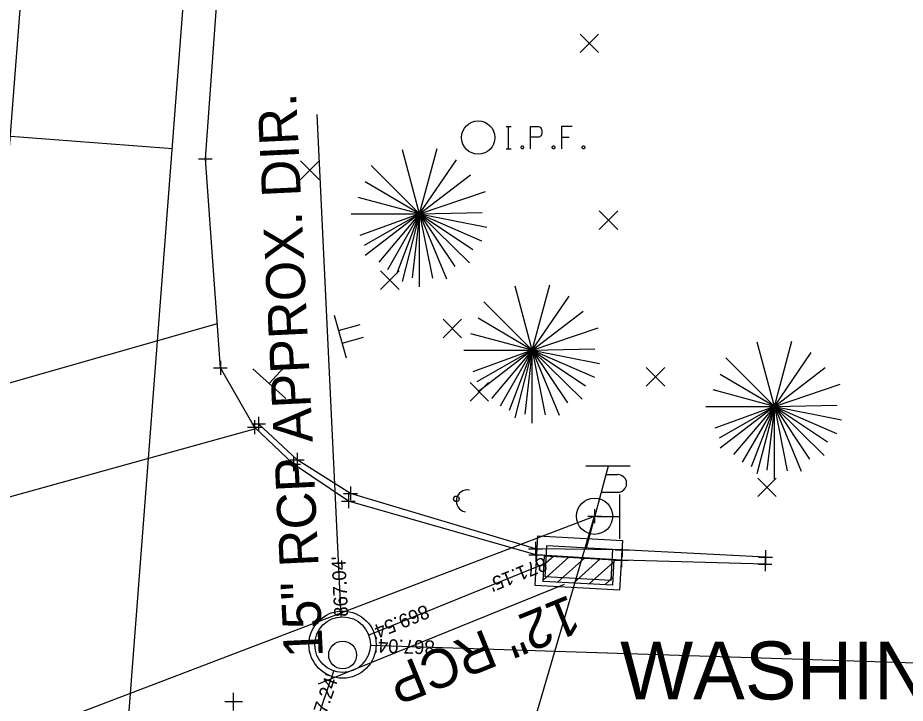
# Model space of a CAD drawing. Extents: x 1380440 to 1381945, y 468756 to 470369.
# Drawn here: x 1381624.1 to 1381687.9, y 470234 to 470283.3 of the extents above; entities that cross this region are included whole.
import ezdxf

# ---------------------------------------------------------------- set-up
doc = ezdxf.new("R2010")
doc.units = 0
for name, color, linetype in [('Animation Elements', 7, 'Continuous'), ('DR_X_Cells', 7, 'Continuous'), ('DV_X_Text', 7, 'Continuous'), ('GE_P_Driveway_CL', 7, 'Continuous'), ('PM_X_Crosswalk', 7, 'Continuous'), ('PV_P_Curb_Ramp', 7, 'Continuous'), ('PV_P_Drive', 7, 'Continuous'), ('PV_P_Joint', 7, 'Continuous'), ('PV_X_COP', 7, 'Continuous'), ('RW_P_Const_Limits', 7, 'Continuous'), ('RW_P_Esmt_TMP', 7, 'Continuous'), ('RW_X_CL', 7, 'Continuous'), ('SC_Scratch1', 7, 'Continuous'), ('SC_Scratch10', 7, 'Continuous'), ('SC_Shading1', 7, 'Continuous'), ('SH_Named_Boundary', 7, 'Continuous'), ('UT_X_Overhead_Combined', 7, 'Continuous'), ('UT_X_Water', 7, 'Continuous'), ('X-CL', 7, 'Continuous')]:
    doc.layers.add(name, color=color, linetype=linetype)

msp = doc.modelspace()

# ---------------------------------------------------------------- linework, layer by layer
at = {"layer": 'Animation Elements'}
msp.add_lwpolyline([(1381657.035, 470218.369), (1381665.562, 470247.404)], dxfattribs=at)
at = {"layer": 'DR_X_Cells'}
msp.add_lwpolyline([(1381677.862, 470244.458), (1381667.541, 470244.981), (1381661.311, 470245.064), (1381647.994, 470249.052), (1381644.157, 470251.471), (1381641.388, 470254.052)], dxfattribs=at)
at = {"layer": 'GE_P_Driveway_CL'}
for p, q in [((1381664.512, 470280.763), (1381665.846, 470282.098)), ((1381664.512, 470282.098), (1381665.846, 470280.763)), ((1381644.396, 470271.637), (1381645.73, 470272.972)), ((1381644.396, 470272.972), (1381645.73, 470271.637)), ((1381665.897, 470268.046), (1381667.231, 470269.381)), ((1381665.897, 470269.381), (1381667.231, 470268.046)), ((1381650.161, 470263.722), (1381651.495, 470265.057)), ((1381650.161, 470265.057), (1381651.495, 470263.722)), ((1381654.657, 470260.249), (1381655.991, 470261.584)), ((1381654.657, 470261.584), (1381655.991, 470260.249)), ((1381669.274, 470256.769), (1381670.608, 470258.104)), ((1381669.274, 470258.104), (1381670.608, 470256.769)), ((1381656.603, 470255.684), (1381657.937, 470257.019)), ((1381656.603, 470257.019), (1381657.937, 470255.684)), ((1381677.295, 470248.818), (1381678.629, 470250.153)), ((1381677.295, 470250.153), (1381678.629, 470248.818))]:
    msp.add_line(p, q, dxfattribs=at)
at = {"layer": 'PM_X_Crosswalk'}
for p, q in [((1381638.406, 470261.247), (1381586.418, 470246.45)), ((1381595.246, 470241.001), (1381641.186, 470253.713))]:
    msp.add_line(p, q, dxfattribs=at)
at = {"layer": 'PV_P_Curb_Ramp'}
for p, q in [((1381664.521, 470245.831), (1381664.521, 470245.831)), ((1381664.485, 470245.166), (1381664.485, 470245.166)), ((1381662.052, 470244.172), (1381662.052, 470244.172)), ((1381664.424, 470244.042), (1381664.424, 470244.042)), ((1381664.444, 470244.417), (1381664.444, 470244.417)), ((1381664.444, 470244.417), (1381664.444, 470244.417)), ((1381666.795, 470243.913), (1381666.795, 470243.913)), ((1381664.362, 470242.919), (1381664.362, 470242.919)), ((1381664.326, 470242.253), (1381664.326, 470242.253)), ((1381647.426, 470240.171), (1381647.426, 470240.171)), ((1381647.426, 470238.171), (1381647.426, 470238.171)), ((1381647.426, 470238.171), (1381647.426, 470238.171)), ((1381647.426, 470237.421), (1381647.426, 470237.421)), ((1381647.426, 470236.171), (1381647.426, 470236.171))]:
    msp.add_line(p, q, dxfattribs=at)
msp.add_circle((1381647.426, 470238.171), 2, dxfattribs=at)
at = {"layer": 'PV_P_Drive'}
for p, q in [((1381647.706, 470258.769), (1381646.84, 470261.849)), ((1381647.143, 470260.771), (1381648.683, 470261.204)), ((1381647.273, 470260.309), (1381647.273, 470260.309)), ((1381647.403, 470259.847), (1381648.943, 470260.28)), ((1381642.156, 470256.945), (1381643.225, 470258.136)), ((1381643.347, 470255.876), (1381640.965, 470258.014)), ((1381667.345, 470248.969), (1381667.345, 470245.769)), ((1381667.345, 470247.369), (1381665.745, 470247.369))]:
    msp.add_line(p, q, dxfattribs=at)
at = {"layer": 'PV_P_Joint'}
for p, q in [((1381661.852, 470242.797), (1381663.699, 470244.458)), ((1381661.914, 470243.928), (1381662.571, 470244.519)), ((1381662.902, 470242.665), (1381664.827, 470244.396)), ((1381664.03, 470242.603), (1381665.955, 470244.334)), ((1381665.158, 470242.542), (1381666.932, 470244.137)), ((1381666.286, 470242.48), (1381666.871, 470243.005))]:
    msp.add_line(p, q, dxfattribs=at)
for points in [[(1381661.484, 470245.998), (1381667.559, 470245.666), (1381667.363, 470242.087), (1381661.289, 470242.42)], [(1381662.114, 470245.295), (1381666.856, 470245.036), (1381666.734, 470242.789), (1381661.991, 470243.049)], [(1381661.948, 470244.553), (1381666.94, 470244.28), (1381666.84, 470242.45), (1381661.848, 470242.723)]]:
    msp.add_lwpolyline(points, close=True, dxfattribs=at)
for centre, radius in [((1381647.426, 470238.171), 2.417), ((1381647.426, 470238.171), 2), ((1381647.426, 470237.421), 1)]:
    msp.add_circle(centre, radius, dxfattribs=at)
at = {"layer": 'PV_X_COP'}
for p, q in [((1381666.525, 470251.004), (1381664.919, 470245.004)), ((1381668.125, 470251.004), (1381664.925, 470251.004)), ((1381666.365, 470250.404), (1381667.215, 470250.404)), ((1381666.024, 470249.129), (1381667.215, 470249.129))]:
    msp.add_line(p, q, dxfattribs=at)
for centre, radius in [((1381655.614, 470248.66), 0.2), ((1381665.562, 470247.404), 1.3)]:
    msp.add_circle(centre, radius, dxfattribs=at)
for centre, radius, start, end in [((1381667.228, 470249.767), 0.638, 268.8767, 91.1233), ((1381656.399, 470248.504), 0.8, 78.74526, 258.74526)]:
    msp.add_arc(centre, radius, start, end, dxfattribs=at)
at = {"layer": 'RW_P_Const_Limits'}
for p, q in [((1381639.582, 470233.429), (1381639.582, 470234.701)), ((1381640.217, 470234.066), (1381638.945, 470234.066))]:
    msp.add_line(p, q, dxfattribs=at)
at = {"layer": 'RW_P_Esmt_TMP'}
msp.add_lwpolyline([(1381677.821, 470243.959), (1381667.493, 470244.246), (1381661.321, 470244.629), (1381647.841, 470248.496), (1381643.906, 470251.149), (1381641.086, 470253.807), (1381638.634, 470258.076), (1381637.552, 470273.11), (1381639.286, 470297.033), (1381641.369, 470320.574)], dxfattribs=at)
at = {"layer": 'RW_X_CL'}
msp.add_line((1381645.705, 470235.349), (1381663.39, 470242.528), dxfattribs=at)
at = {"layer": 'SC_Scratch1'}
for points in [[(1381659.198, 470275.448), (1381659.551, 470275.448)], [(1381659.375, 470273.848), (1381659.375, 470275.448)], [(1381660.94, 470273.848), (1381660.94, 470275.448), (1381661.469, 470275.448), (1381661.524, 470275.435), (1381661.601, 470275.41), (1381661.635, 470275.385), (1381661.668, 470275.36), (1381661.712, 470275.297), (1381661.745, 470275.234), (1381661.767, 470275.133), (1381661.767, 470274.982), (1381661.756, 470274.931), (1381661.734, 470274.856), (1381661.69, 470274.768), (1381661.645, 470274.73), (1381661.612, 470274.705), (1381661.557, 470274.679), (1381661.469, 470274.667), (1381660.94, 470274.667)], [(1381663.949, 470275.448), (1381663.189, 470275.448), (1381663.189, 470273.848)], [(1381663.189, 470274.667), (1381663.729, 470274.667)], [(1381660.334, 470274.062), (1381660.389, 470274.062), (1381660.422, 470274.037), (1381660.455, 470273.987), (1381660.455, 470273.924), (1381660.422, 470273.873), (1381660.389, 470273.848), (1381660.334, 470273.848), (1381660.301, 470273.873), (1381660.268, 470273.924), (1381660.268, 470273.987), (1381660.301, 470274.037), (1381660.334, 470274.062)], [(1381662.583, 470274.062), (1381662.638, 470274.062), (1381662.671, 470274.037), (1381662.704, 470273.987), (1381662.704, 470273.924), (1381662.671, 470273.873), (1381662.638, 470273.848), (1381662.583, 470273.848), (1381662.549, 470273.873), (1381662.516, 470273.924), (1381662.516, 470273.987), (1381662.549, 470274.037), (1381662.583, 470274.062)], [(1381664.732, 470274.062), (1381664.787, 470274.062), (1381664.82, 470274.037), (1381664.853, 470273.987), (1381664.853, 470273.924), (1381664.82, 470273.873), (1381664.787, 470273.848), (1381664.732, 470273.848), (1381664.699, 470273.873), (1381664.666, 470273.924), (1381664.666, 470273.987), (1381664.699, 470274.037), (1381664.732, 470274.062)], [(1381659.198, 470273.848), (1381659.551, 470273.848)]]:
    msp.add_lwpolyline(points, dxfattribs=at)
msp.add_circle((1381657.184, 470274.648), 1.2, dxfattribs=at)
at = {"layer": 'SC_Scratch10'}
for p, q in [((1381652.969, 470269.158), (1381651.734, 470273.772)), ((1381652.969, 470269.158), (1381654.226, 470273.857)), ((1381652.969, 470269.158), (1381655.624, 470273.043)), ((1381652.969, 470269.158), (1381649.479, 470272.645)), ((1381652.969, 470269.158), (1381649.062, 470271.455)), ((1381652.969, 470269.158), (1381656.626, 470271.963)), ((1381652.969, 470269.158), (1381648.556, 470270.342)), ((1381652.969, 470269.158), (1381657.706, 470270.765)), ((1381648.034, 470269.158), (1381652.969, 470269.158)), ((1381652.969, 470269.158), (1381648.679, 470267.597)), ((1381652.969, 470269.158), (1381648.986, 470266.877)), ((1381652.969, 470269.158), (1381649.062, 470266.163)), ((1381652.969, 470269.158), (1381650.024, 470265.692)), ((1381652.969, 470269.158), (1381650.651, 470265.143)), ((1381652.969, 470269.158), (1381651.304, 470264.818)), ((1381652.969, 470269.158), (1381651.706, 470264.302)), ((1381652.969, 470269.158), (1381652.427, 470264.567)), ((1381652.969, 470269.158), (1381657.479, 470269.25)), ((1381652.969, 470263.918), (1381652.969, 470269.158)), ((1381652.969, 470269.158), (1381653.891, 470264.522)), ((1381652.969, 470269.158), (1381654.902, 470264.49)), ((1381652.969, 470269.158), (1381655.506, 470265.365)), ((1381652.969, 470269.158), (1381656.557, 470265.637)), ((1381652.969, 470269.158), (1381656.791, 470266.603)), ((1381652.969, 470269.158), (1381657.434, 470267.217)), ((1381652.969, 470269.158), (1381657.797, 470268.2)), ((1381661.078, 470259.349), (1381659.843, 470263.963)), ((1381661.078, 470259.349), (1381662.335, 470264.048)), ((1381661.078, 470259.349), (1381663.733, 470263.234)), ((1381661.078, 470259.349), (1381657.588, 470262.836)), ((1381661.078, 470259.349), (1381664.735, 470262.154)), ((1381661.078, 470259.349), (1381657.171, 470261.646)), ((1381661.078, 470259.349), (1381665.815, 470260.956)), ((1381661.078, 470259.349), (1381656.665, 470260.533)), ((1381678.497, 470255.307), (1381679.754, 470260.005)), ((1381656.143, 470259.349), (1381661.078, 470259.349)), ((1381661.078, 470259.349), (1381656.788, 470257.788)), ((1381661.078, 470259.349), (1381657.095, 470257.068)), ((1381661.078, 470259.349), (1381657.171, 470256.354)), ((1381661.078, 470259.349), (1381658.133, 470255.883)), ((1381661.078, 470259.349), (1381658.76, 470255.334)), ((1381661.078, 470259.349), (1381659.413, 470255.009)), ((1381661.078, 470259.349), (1381659.815, 470254.493)), ((1381661.078, 470259.349), (1381660.536, 470254.758)), ((1381661.078, 470259.349), (1381665.588, 470259.441)), ((1381661.078, 470254.109), (1381661.078, 470259.349)), ((1381661.078, 470259.349), (1381662, 470254.713)), ((1381661.078, 470259.349), (1381663.011, 470254.681)), ((1381661.078, 470259.349), (1381663.615, 470255.556)), ((1381661.078, 470259.349), (1381664.666, 470255.828)), ((1381661.078, 470259.349), (1381664.9, 470256.794)), ((1381661.078, 470259.349), (1381665.543, 470257.408)), ((1381661.078, 470259.349), (1381665.906, 470258.391)), ((1381678.497, 470255.307), (1381677.262, 470259.92)), ((1381678.497, 470255.307), (1381675.007, 470258.793)), ((1381678.497, 470255.307), (1381681.152, 470259.192)), ((1381678.497, 470255.307), (1381682.154, 470258.112)), ((1381678.497, 470255.307), (1381674.59, 470257.603)), ((1381678.497, 470255.307), (1381683.234, 470256.913)), ((1381678.497, 470255.307), (1381674.084, 470256.49)), ((1381673.562, 470255.307), (1381678.497, 470255.307)), ((1381678.497, 470255.307), (1381674.207, 470253.745)), ((1381678.497, 470255.307), (1381674.514, 470253.025)), ((1381678.497, 470255.307), (1381674.59, 470252.312)), ((1381678.497, 470255.307), (1381675.552, 470251.84)), ((1381678.497, 470255.307), (1381676.179, 470251.292)), ((1381678.497, 470255.307), (1381676.832, 470250.967)), ((1381678.497, 470255.307), (1381677.234, 470250.45)), ((1381678.497, 470255.307), (1381677.955, 470250.715)), ((1381678.497, 470255.307), (1381683.007, 470255.398)), ((1381678.497, 470250.067), (1381678.497, 470255.307)), ((1381678.497, 470255.307), (1381679.419, 470250.67)), ((1381678.497, 470255.307), (1381680.43, 470250.638)), ((1381678.497, 470255.307), (1381681.034, 470251.513)), ((1381678.497, 470255.307), (1381682.085, 470251.785)), ((1381678.497, 470255.307), (1381682.319, 470252.752)), ((1381678.497, 470255.307), (1381682.962, 470253.365)), ((1381678.497, 470255.307), (1381683.325, 470254.348))]:
    msp.add_line(p, q, dxfattribs=at)
at = {"layer": 'SC_Shading1'}
msp.add_lwpolyline([(1381627.408, 470324.235), (1381625.025, 470294.425), (1381622.344, 470259.947), (1381618.765, 470220.138), (1381616.919, 470200.188), (1381615.103, 470178.831), (1381610.946, 470124.776), (1381606.492, 470071.232), (1381602.26, 470019.361), (1381598.177, 469969.796), (1381595.011, 469928.064), (1381590.91, 469878.811), (1381589.36, 469859.114), (1381585.986, 469815.579)], dxfattribs=at)
at = {"layer": 'SH_Named_Boundary'}
for p, q in [((1381637.552, 470273.61), (1381637.552, 470272.61)), ((1381637.052, 470273.11), (1381638.052, 470273.11)), ((1381637.552, 470273.11), (1381637.552, 470273.11)), ((1381638.134, 470258.076), (1381639.134, 470258.076)), ((1381638.634, 470258.576), (1381638.634, 470257.576)), ((1381638.634, 470258.076), (1381638.634, 470258.076)), ((1381641.086, 470254.307), (1381641.086, 470253.307)), ((1381641.388, 470254.552), (1381641.388, 470253.552)), ((1381640.586, 470253.807), (1381641.586, 470253.807)), ((1381640.888, 470254.052), (1381641.888, 470254.052)), ((1381641.086, 470253.807), (1381641.086, 470253.807)), ((1381641.388, 470254.052), (1381641.388, 470254.052)), ((1381643.906, 470251.649), (1381643.906, 470250.649)), ((1381643.906, 470251.649), (1381643.906, 470250.649)), ((1381644.157, 470251.971), (1381644.157, 470250.971)), ((1381644.157, 470251.971), (1381644.157, 470250.971)), ((1381643.406, 470251.149), (1381644.406, 470251.149)), ((1381643.406, 470251.149), (1381644.406, 470251.149)), ((1381643.657, 470251.471), (1381644.657, 470251.471)), ((1381643.657, 470251.471), (1381644.657, 470251.471)), ((1381643.906, 470251.149), (1381643.906, 470251.149)), ((1381643.906, 470251.149), (1381643.906, 470251.149)), ((1381644.157, 470251.471), (1381644.157, 470251.471)), ((1381644.157, 470251.471), (1381644.157, 470251.471)), ((1381647.994, 470249.552), (1381647.994, 470248.552)), ((1381647.341, 470248.496), (1381648.341, 470248.496)), ((1381647.494, 470249.052), (1381648.494, 470249.052)), ((1381647.841, 470248.996), (1381647.841, 470247.996)), ((1381647.841, 470248.496), (1381647.841, 470248.496)), ((1381647.994, 470249.052), (1381647.994, 470249.052)), ((1381665.562, 470247.904), (1381665.562, 470246.904)), ((1381665.562, 470247.904), (1381665.562, 470246.904)), ((1381665.562, 470247.904), (1381665.562, 470246.904)), ((1381665.562, 470247.904), (1381665.562, 470246.904)), ((1381665.562, 470247.904), (1381665.562, 470246.904)), ((1381665.062, 470247.404), (1381666.062, 470247.404)), ((1381665.062, 470247.404), (1381666.062, 470247.404)), ((1381665.062, 470247.404), (1381666.062, 470247.404)), ((1381665.062, 470247.404), (1381666.062, 470247.404)), ((1381665.062, 470247.404), (1381666.062, 470247.404)), ((1381665.562, 470247.404), (1381665.562, 470247.404)), ((1381665.562, 470247.404), (1381665.562, 470247.404)), ((1381665.562, 470247.404), (1381665.562, 470247.404)), ((1381665.562, 470247.404), (1381665.562, 470247.404)), ((1381665.562, 470247.404), (1381665.562, 470247.404)), ((1381661.311, 470245.564), (1381661.311, 470244.564)), ((1381661.311, 470245.564), (1381661.311, 470244.564)), ((1381667.541, 470245.481), (1381667.541, 470244.481)), ((1381660.811, 470245.064), (1381661.811, 470245.064)), ((1381660.811, 470245.064), (1381661.811, 470245.064)), ((1381660.821, 470244.629), (1381661.821, 470244.629)), ((1381660.821, 470244.629), (1381661.821, 470244.629)), ((1381661.311, 470245.064), (1381661.311, 470245.064)), ((1381661.311, 470245.064), (1381661.311, 470245.064)), ((1381661.321, 470245.129), (1381661.321, 470244.129)), ((1381661.321, 470245.129), (1381661.321, 470244.129)), ((1381661.321, 470244.629), (1381661.321, 470244.629)), ((1381661.321, 470244.629), (1381661.321, 470244.629)), ((1381667.041, 470244.981), (1381668.041, 470244.981)), ((1381667.493, 470244.746), (1381667.493, 470243.746)), ((1381667.541, 470244.981), (1381667.541, 470244.981)), ((1381677.862, 470244.958), (1381677.862, 470243.958)), ((1381666.993, 470244.246), (1381667.993, 470244.246)), ((1381667.493, 470244.246), (1381667.493, 470244.246)), ((1381677.362, 470244.458), (1381678.362, 470244.458)), ((1381677.821, 470244.459), (1381677.821, 470243.459)), ((1381677.862, 470244.458), (1381677.862, 470244.458)), ((1381677.321, 470243.959), (1381678.321, 470243.959)), ((1381677.821, 470243.959), (1381677.821, 470243.959))]:
    msp.add_line(p, q, dxfattribs=at)
at = {"layer": 'UT_X_Overhead_Combined'}
msp.add_lwpolyline([(1381540.8, 469054.263), (1381515.279, 469203.101), (1381529.165, 469390.12), (1381543.86, 469565.781), (1381559.775, 469757.408), (1381571.968, 469887.64), (1381581.264, 470018.199), (1381595.795, 470220.833), (1381665.562, 470247.404)], dxfattribs=at)
at = {"layer": 'UT_X_Water'}
for p, q in [((1381630.263, 470209.692), (1381638.864, 470321.963)), ((1381635.177, 470273.837), (1381538.109, 470281.273))]:
    msp.add_line(p, q, dxfattribs=at)
at = {"layer": 'X-CL'}
for p, q in [((1381647.33, 470240.169), (1381645.602, 470276.308)), ((1381662.069, 470244.042), (1381649.304, 470238.86)), ((1381940.268, 470228.716), (1381649.425, 470238.106)), ((1381633.903, 470198.558), (1381646.794, 470236.273))]:
    msp.add_line(p, q, dxfattribs=at)

# ---------------------------------------------------------------- texts
at = {"layer": 'DV_X_Text'}
msp.add_text('WASHINGTON AVE.', height=4.16667, dxfattribs=at).set_placement((1381667.396, 470234.228))
at = {"layer": 'RW_X_CL'}
for s, rotation, p in [('15" RCP APPROX. DIR.', 92.73872, (1381646.018, 470237.293)), ('12" RCP', 202.09342, (1381663.755, 470241.787))]:
    msp.add_text(s, height=2.8, rotation=rotation, dxfattribs=at).set_placement(p)
at = {"layer": 'SC_Scratch1'}
for s, rotation, p in [("867.04'", 92.73872, (1381647.83, 470240.193)), ("871.15'", 202.09342, (1381661.881, 470244.505)), ("869.54'", 202.09342, (1381653.408, 470241.066)), ("867.04'", 178.15078, (1381654.071, 470238.457)), ("867.24'", 71.12967, (1381645.769, 470231.728))]:
    msp.add_text(s, height=1, rotation=rotation, dxfattribs=at).set_placement(p)

doc.saveas('drawing.dxf')
